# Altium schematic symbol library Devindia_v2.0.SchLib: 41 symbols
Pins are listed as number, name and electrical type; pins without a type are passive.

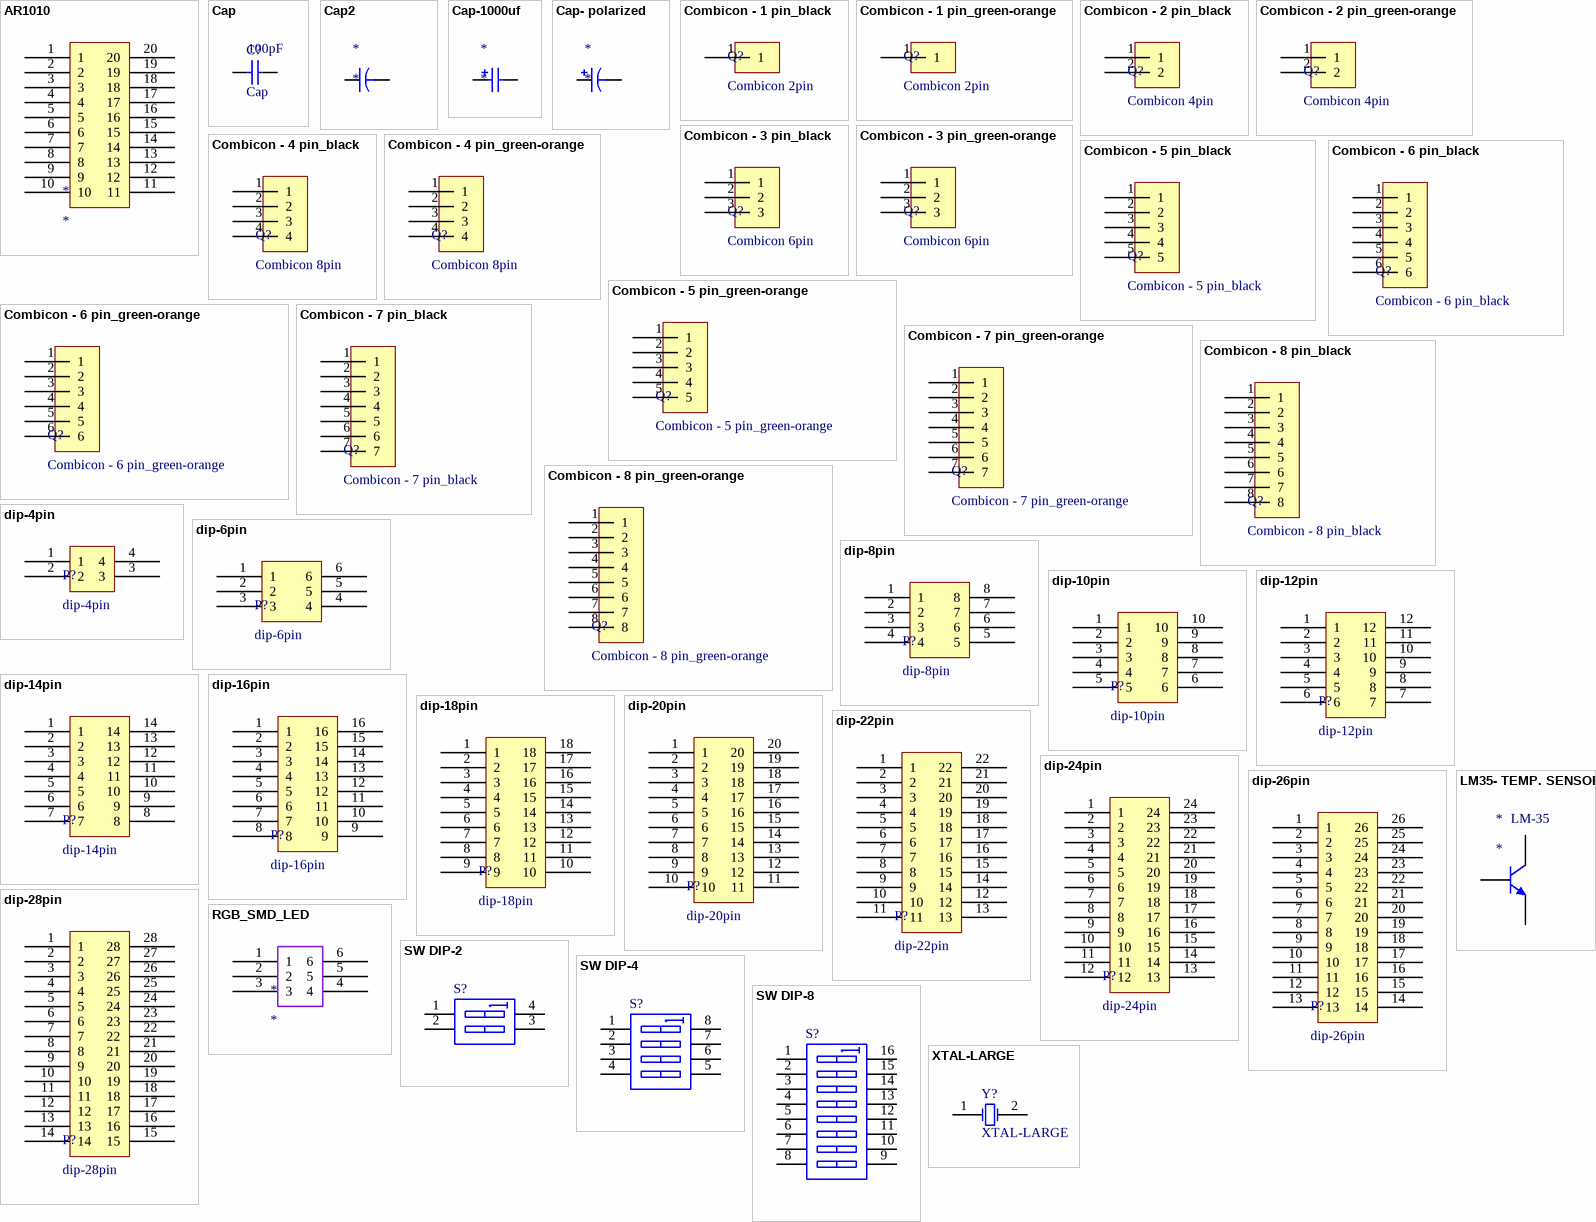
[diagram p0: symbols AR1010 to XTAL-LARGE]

## AR1010
designator *
footprint AR1010
pins: 1, 2, 3, 4, 5, 6, 7, 8, 9, 10, 11, 12, 13, 14, 15, 16, 17, 18, 19, 20

## Cap
designator C?  value 100pF
Capacitor
footprint Cap
footprint CAPR2.54-5.1x3.2 (Capacitor, Ceramic, Thru-Hole, Dipped Radial; Body 5.1 x 3.2 mm (WxT) Pin Spacing 2.54 mm (typ))
footprint CAPR5.08-7.8x3.2 (Capacitor, Ceramic, Thru-Hole, Dipped Radial; Body 7.8 x 3.2 mm (WxT) Pin Spacing 5.08 mm (typ))
simulation model CAP (Capacitor)
signal-integrity model Cap
pins: 1, 2

## Cap2
designator *
pins: 1, 2

## Cap-1000uf
designator *
pins: 1, 2

## Cap- polarized
designator *
pins: 1, 2

## Combicon - 1 pin_black
designator Q?, comment Combicon 2pin
footprint Combicon - 2 pin
pins: 1

## Combicon - 1 pin_green-orange
designator Q?, comment Combicon 2pin
footprint Combicon - 2 pin
pins: 1

## Combicon - 2 pin_black
designator Q?, comment Combicon 4pin
footprint Combicon - 4pin
pins: 1, 2

## Combicon - 2 pin_green-orange
designator Q?, comment Combicon 4pin
footprint Combicon - 4pin
pins: 1, 2

## Combicon - 3 pin_black
designator Q?, comment Combicon 6pin
footprint Combicon - 6pin
pins: 1, 2, 3

## Combicon - 3 pin_green-orange
designator Q?, comment Combicon 6pin
footprint Combicon - 6pin
pins: 1, 2, 3

## Combicon - 4 pin_black
designator Q?, comment Combicon 8pin
footprint Combicon - 8pin
pins: 1, 2, 3, 4

## Combicon - 4 pin_green-orange
designator Q?, comment Combicon 8pin
footprint Combicon - 8pin
pins: 1, 2, 3, 4

## Combicon - 5 pin_black
designator Q?
footprint Combicon - 10 pin
pins: 1, 2, 3, 4, 5

## Combicon - 5 pin_green-orange
designator Q?
footprint Combicon - 10 pin
pins: 1, 2, 3, 4, 5

## Combicon - 6 pin_black
designator Q?
footprint Combicon - 12pin
pins: 1, 2, 3, 4, 5, 6

## Combicon - 6 pin_green-orange
designator Q?
footprint Combicon - 12pin
pins: 1, 2, 3, 4, 5, 6

## Combicon - 7 pin_black
designator Q?
footprint Combicon - 14pin
pins: 1, 2, 3, 4, 5, 6, 7

## Combicon - 7 pin_green-orange
designator Q?
footprint Combicon - 14pin
pins: 1, 2, 3, 4, 5, 6, 7

## Combicon - 8 pin_black
designator Q?
footprint Combicon - 16pin
pins: 1, 2, 3, 4, 5, 6, 7, 8

## Combicon - 8 pin_green-orange
designator Q?
footprint Combicon - 16pin
pins: 1, 2, 3, 4, 5, 6, 7, 8

## dip-4pin
designator P?
footprint dip-4pin
pins: 1, 2, 3, 4

## dip-6pin
designator P?
footprint dip-6pin
pins: 1, 2, 3, 4, 5, 6

## dip-8pin
designator P?
footprint dip-8pin
pins: 1, 2, 3, 4, 5, 6, 7, 8

## dip-10pin
designator P?
footprint dip-10pin
pins: 1, 2, 3, 4, 5, 6, 7, 8, 9, 10

## dip-12pin
designator P?
footprint dip-12pin
pins: 1, 2, 3, 4, 5, 6, 7, 8, 9, 10, 11, 12

## dip-14pin
designator P?
footprint dip-14pin
pins: 1, 2, 3, 4, 5, 6, 7, 8, 9, 10, 11, 12, 13, 14

## dip-16pin
designator P?
footprint dip-16pin
pins: 1, 2, 3, 4, 5, 6, 7, 8, 9, 10, 11, 12, 13, 14, 15, 16

## dip-18pin
designator P?
footprint dip-18pin
pins: 1, 2, 3, 4, 5, 6, 7, 8, 9, 10, 11, 12, 13, 14, 15, 16, 17, 18

## dip-20pin
designator P?
footprint dip-20pin
pins: 1, 2, 3, 4, 5, 6, 7, 8, 9, 10, 11, 12, 13, 14, 15, 16, 17, 18, 19, 20

## dip-22pin
designator P?
footprint dip-22pin
pins: 1, 2, 3, 4, 5, 6, 7, 8, 9, 10, 11, 12, 13, 14, 15, 16, 17, 18, 19, 20, 21, 22

## dip-24pin
designator P?
footprint dip-24pin
pins: 1, 2, 3, 4, 5, 6, 7, 8, 9, 10, 11, 12, 13, 14, 15, 16, 17, 18, 19, 20, 21, 22, 23, 24

## dip-26pin
designator P?
footprint dip-26pin
pins: 1, 2, 3, 4, 5, 6, 7, 8, 9, 10, 11, 12, 13, 14, 15, 16, 17, 18, 19, 20, 21, 22, 23, 24, 25, 26

## dip-28pin
designator P?
footprint dip-28pin
pins: 1, 2, 3, 4, 5, 6, 7, 8, 9, 10, 11, 12, 13, 14, 15, 16, 17, 18, 19, 20, 21, 22, 23, 24, 25, 26, 27, 28

## LM35- TEMP. SENSOR
designator *
pins: 1 E, 2 B, 3 C

## RGB_SMD_LED
designator *
footprint RGB_SMD_LED
pins: 1, 2, 3, 4, 5, 6

## SW DIP-2
designator S?
DIP Switch, 2 Position, SPST
footprint DIP-4 (DIP; 4 Leads; Row Spacing 7.62 mm; Pitch 2.54 mm)
simulation model dpsw2 (Spice Subcircuit)
pins: 1 A1, 2 A2, 3 B2, 4 B1

## SW DIP-4
designator S?
DIP Switch, 4 Position, SPST
footprint SOIC127P600-8N (SOIC, 8-Leads, Body 4.9x3.9mm, Pitch 1.27mm, IPC Medium Density)
footprint SOIC127P600-8L (SOIC, 8-Leads, Body 4.9x3.9mm, Pitch 1.27mm, IPC High Density)
footprint SOIC127P600-8M (SOIC, 8-Leads, Body 4.9x3.9mm, Pitch 1.27mm, IPC Low Density)
simulation model dpsw4 (Spice Subcircuit)
pins: 1 A1, 2 A2, 3 A3, 4 A4, 5 B4, 6 B3, 7 B2, 8 B1

## SW DIP-8
designator S?
DIP Switch, 8 Position, SPST
footprint DIP_SW_8WAY_SMD (DIP Switch; 16 Leads)
simulation model dpsw8 (Spice Subcircuit)
pins: 1 A1, 2 A2, 3 A3, 4 A4, 5 A5, 6 A6, 7 A7, 8 A8, 9 B8, 10 B7, 11 B6, 12 B5, 13 B4, 14 B3, 15 B2, 16 B1

## XTAL-LARGE
designator Y?
Crystal Oscillator
footprint CRYSTAL3
simulation model XTAL (Spice Subcircuit)
pins: 1 OSC1, 2 OSC2

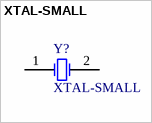
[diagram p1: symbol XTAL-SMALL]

## XTAL-SMALL
designator Y?
Crystal Oscillator
footprint CRYSTAL1
simulation model XTAL (Spice Subcircuit)
pins: 1 OSC1, 2 OSC2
